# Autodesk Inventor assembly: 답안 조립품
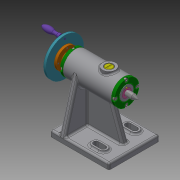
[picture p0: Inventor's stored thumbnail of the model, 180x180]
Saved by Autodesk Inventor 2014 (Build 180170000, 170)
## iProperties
Created: 2019-10
Part Number: 답안 조립품
Document SubType Name: Assembly
Designer: kh
Author: kh
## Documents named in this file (18)
- C:\Users\kh\Desktop\491004V1005\답안 조립품.iam
- C:\Users\kh\Desktop\491004V1005\본체.ipt
- C:\Users\kh\Desktop\491004V1005\나사.ipt
- C:\Users\kh\Desktop\491004V1005\나사축.ipt
- C:\Users\kh\Desktop\491004V1005\너트 M8.ipt
- C:\Users\kh\Desktop\491004V1005\돌림판.ipt
- C:\Users\kh\Desktop\491004V1005\멈춤나사 M3.ipt
- C:\Users\kh\Desktop\491004V1005\볼트 M3.ipt
- C:\Users\kh\Desktop\491004V1005\부시.ipt
- C:\Users\kh\Desktop\491004V1005\센터.ipt
- C:\Users\kh\Desktop\491004V1005\센터홀더.ipt
- C:\Users\kh\Desktop\491004V1005\슬리브.ipt
- C:\Users\kh\Desktop\491004V1005\와셔.ipt
- C:\Users\kh\Desktop\491004V1005\중공축.ipt
- C:\Users\kh\Desktop\491004V1005\커버.ipt
- C:\Users\kh\Desktop\491004V1005\키 4 x 4 x 10.ipt
- C:\Users\kh\Desktop\491004V1005\플랜지.ipt
- C:\Users\kh\Desktop\491004V1005\핸들.ipt
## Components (2 placed, 2 different names)
1. 플랜지:1 — Insert:12, Mate:4, Insert:13, Insert:14, Insert:16
2. 핸들:1 — Insert:17, Angle:10
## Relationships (7: Insert 5, Mate 1, Angle 1)
- Insert:12: 플랜지:1
- Mate:4: 플랜지:1
- Insert:13: 플랜지:1
- Insert:14: 플랜지:1
- Insert:16: 플랜지:1
- Insert:17: 핸들:1
- Angle:10: 핸들:1
